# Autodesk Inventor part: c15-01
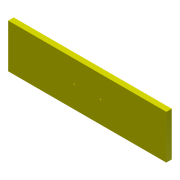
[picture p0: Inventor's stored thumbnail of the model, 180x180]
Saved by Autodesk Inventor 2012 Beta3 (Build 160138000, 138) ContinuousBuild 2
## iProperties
Created: 2011-02
Part Number: c15-01
Material: Default
Document SubType Name: Modeling
Designer: Beta-8540w
Density: 1 g/cm^3
Author: Beta-8540w
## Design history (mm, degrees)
sketch "Sketch1"
  geometry: L1 (-228.6, -63.5)-(228.6, -63.5); L2 (228.6, -63.5)-(228.6, 63.5); L3 (228.6, 63.5)-(-228.6, 63.5); L4 (-228.6, 63.5)-(-228.6, -63.5); 3 further points
  constraints: 8 end point, 2 midpoint, 2 parallel, 1 horizontal, 1 horizontal alignment, 1 perpendicular, 1 vertical alignment
  dimensions: "d0" = 457.2 distance of L3.end L2.end; "d1" = 127 distance of L2.end L1.end
extrude "Drawer Face" new body sketch "Sketch1" distance "d2" = 15.875; taper "d3" = 0 deg
sketch "Sketch2"
  geometry: 1 further point
hole "Single Hole Pull" sketch "Sketch2" at (0, 0) diameter "d4" = 4.4958; stored, may be unused: countersink angle "d8" = 82 deg, drill point angle "d10" = 118 deg; dims "d5" = 19.05, "d9" = 25.4, "d72" = 8.4328, "d73" = 6.35
sketch "Sketch3"
  geometry: L1 (-38.1, 0)-(38.1, 0); 2 further points
  constraints: 2 end point, 1 coincident, 1 horizontal, 1 midpoint
  dimensions: "d6" = 76.2 distance of L1.start L1.end
hole "Double Hole Pull" sketch "Sketch3" at (-38.1, 0), (38.1, 0) diameter "d7" = 4.4958; stored, may be unused: countersink angle "d16" = 82 deg, drill point angle "d18" = 118 deg; dims "d13" = 19.05, "d14" = 8.4328, "d15" = 6.35, "d17" = 25.4
body "Solid1"
